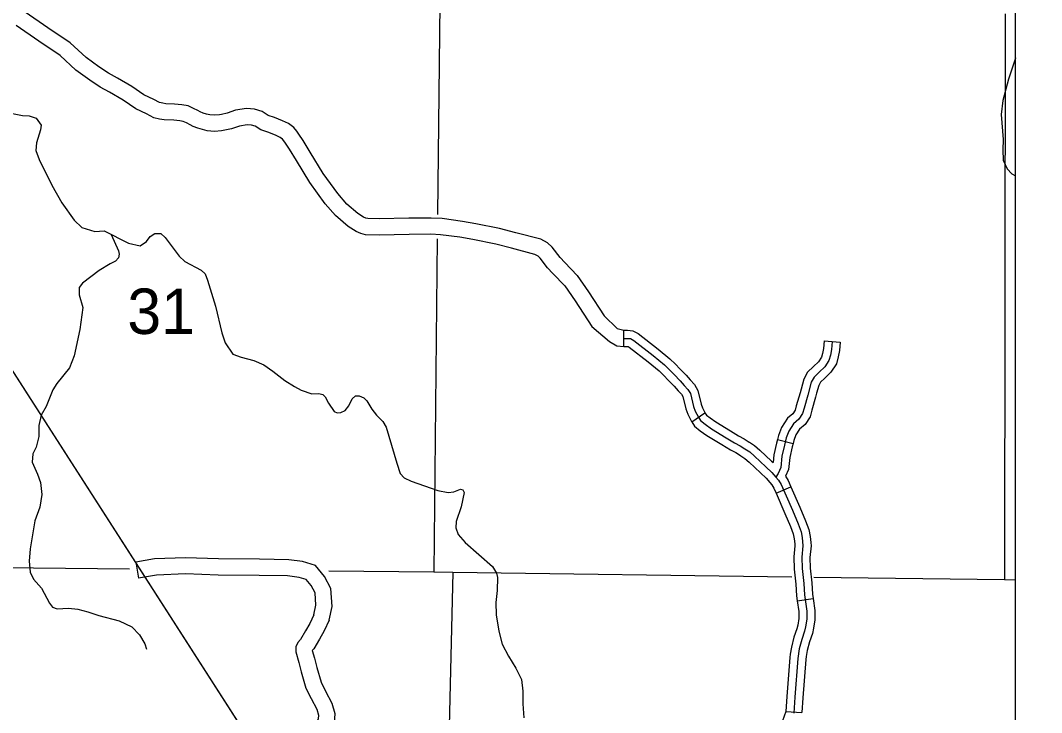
# Model space of a CAD drawing. Extents: x 0 to 3171, y 0 to 2059.
# Drawn here: x 1965.7 to 2123.9, y 1087.6 to 1194.8 of the extents above; entities that cross this region are included whole.
import ezdxf

# ---------------------------------------------------------------- set-up
doc = ezdxf.new("R2010")
doc.units = 0
for name, color, linetype in [('Default', 7, 'Continuous'), ('Level 35', 7, 'Continuous'), ('Level 4', 7, 'Continuous'), ('Level 45', 7, 'Continuous'), ('Level 46', 7, 'Continuous'), ('Level 5', 7, 'Continuous')]:
    doc.layers.add(name, color=color, linetype=linetype)

msp = doc.modelspace()

# ---------------------------------------------------------------- linework, layer by layer
at = {"layer": 'Default'}
msp.add_line((2119.81, 254.41), (2119.81, 1254.61), dxfattribs=at)
msp.add_lwpolyline([(2119.81, 1254.61), (1029.42, 1254.61), (1029.42, 254.41), (2119.81, 254.41)], close=True, dxfattribs=at)
msp.add_lwpolyline([(2119.81, 1254.61), (1029.42, 1254.61), (1029.42, 254.41), (2119.81, 254.41)], close=True, dxfattribs=at)
msp.add_lwpolyline([(2119.81, 1254.61), (1029.42, 1254.61), (1029.42, 254.41), (2119.81, 254.41)], close=True, dxfattribs=at)
for points in [[(1931.87, 1191.31), (2273.76, 658.86), (2637.04, 658.32)], [(1931.87, 1191.31), (2119.81, 898.62)]]:
    msp.add_lwpolyline(points, dxfattribs=at)
at = {"layer": 'Level 35'}
for points in [[(2119.81, 1189), (2119.8, 1188.95), (2118.71, 1185.67), (2117.83, 1182.41), (2117.59, 1180.23), (2117.92, 1176.37), (2117.86, 1174.76), (2117.91, 1173.16), (2118.5, 1171.83), (2119.26, 1171.04), (2119.81, 1170.7)], [(1964.24, 1180.44), (1966.09, 1180.09), (1967.12, 1179.99), (1968.18, 1179.67), (1968.94, 1178.59), (1968.83, 1177.84), (1968.26, 1175.81), (1968.14, 1174.63), (1968.63, 1173.23), (1970.63, 1169.27), (1972.16, 1166.53), (1974.08, 1163.85), (1975.24, 1162.73), (1977.26, 1162.1), (1978.71, 1162.19), (1982.5, 1160.31), (1984.27, 1159.87), (1985.28, 1160.53), (1985.84, 1161.32), (1986.56, 1161.8), (1987.48, 1161.79), (1988.15, 1161.17), (1990.32, 1158.29), (1991.2, 1157.48), (1993.73, 1156.09), (1994.34, 1155.55), (1994.72, 1154.59), (1995.97, 1150.53), (1996.94, 1146.4), (1997.44, 1144.84), (1998.66, 1143.1), (1999.9, 1142.65), (2001.87, 1142.12), (2003.41, 1141.46), (2004.84, 1140.48), (2006.69, 1139.05), (2008.17, 1138.1), (2009.21, 1137.54), (2010.89, 1136.96), (2011.95, 1137.04), (2012.55, 1136.86), (2012.92, 1136.52), (2013.47, 1135.51), (2014.32, 1134.25), (2014.8, 1134.04), (2015.37, 1134.06), (2016.02, 1134.37), (2016.59, 1135.13), (2017.13, 1136.17), (2017.62, 1136.64), (2018.2, 1136.66), (2018.94, 1136.37), (2019.36, 1135.89), (2020.15, 1134.59), (2020.87, 1133.66), (2021.87, 1132.69), (2022.4, 1131.78), (2024.02, 1126.22), (2024.55, 1124.64), (2025.15, 1123.95), (2026.23, 1123.46), (2030.35, 1121.99), (2031.97, 1121.68), (2032.84, 1121.81), (2033.91, 1122.2), (2034.27, 1122.09), (2034.47, 1121.71), (2033.97, 1119.48), (2033.21, 1117.17), (2033.14, 1116.19)], [(1979.82, 1161.63), (1980.92, 1159.11), (1981.02, 1158.59), (1980.93, 1158.01), (1980.49, 1157.52), (1979.63, 1157.11), (1977.94, 1156.05), (1976.65, 1155.09), (1975.35, 1154.09), (1974.86, 1153.43), (1974.84, 1152.28), (1975.39, 1150.35), (1974.97, 1146.94), (1974.07, 1142.87), (1973.33, 1140.98), (1971.38, 1138.59), (1970.76, 1137.56), (1969.71, 1134.98), (1968.96, 1133.67), (1968.61, 1132.06), (1968.62, 1130.36), (1968.19, 1128.72), (1967.65, 1127.69), (1967.57, 1126.39), (1968.37, 1124.55), (1968.84, 1123.24), (1969.06, 1121.4), (1968.74, 1119.41), (1967.96, 1117.32), (1967.27, 1112.97), (1967.11, 1111.03), (1967.25, 1109.37), (1967.79, 1108.26), (1969.01, 1106.89), (1970.24, 1104.55), (1970.73, 1103.94), (1971.45, 1103.69), (1973.2, 1103.75), (1974.65, 1103.62), (1976.17, 1103.22), (1977.89, 1102.62), (1981.04, 1101.82), (1982.98, 1100.9), (1984.16, 1099.64), (1985.03, 1098.23), (1985.29, 1097.42)], [(2033.14, 1116.19), (2033.5, 1115.17), (2034.6, 1113.93), (2038.85, 1110.21), (2039.48, 1109.2), (2039.6, 1108.55), (2039.54, 1106.5), (2039.37, 1104.63), (2039.39, 1102.73), (2039.81, 1100.2), (2040.36, 1098.18), (2041.3, 1096.34), (2042.46, 1094.5), (2043.33, 1092.71), (2043.51, 1090.91), (2043.53, 1088.98), (2043.67, 1086.79)]]:
    msp.add_lwpolyline(points, dxfattribs=at)
at = {"layer": 'Level 4'}
for points in [[(1982.64, 1109.82), (1952.86, 1110.13)], [(2085.16, 1108.59), (2032.69, 1109.29), (2029.77, 1109.33), (2013.52, 1109.5)], [(2119.81, 1108.12), (2118.11, 1108.14), (2088.58, 1108.54)]]:
    msp.add_lwpolyline(points, dxfattribs=at)
at = {"layer": 'Level 45'}
for p, q in [((2059.17, 1144.3), (2059.17, 1146.8)), ((2090.17, 1145.16), (2092.66, 1144.99)), ((2069.69, 1132.61), (2071.74, 1134.03)), ((2082.95, 1129.88), (2085.38, 1129.29)), ((2082.76, 1121.58), (2085.05, 1122.58)), ((2086.02, 1104.91), (2088.5, 1105.25)), ((2084.24, 1087.78), (2086.73, 1087.61))]:
    msp.add_line(p, q, dxfattribs=at)
for points in [[(2059.17, 1146.8), (2059.73, 1146.8), (2060.58, 1146.73), (2061.39, 1146.29), (2064.48, 1143.86), (2066.31, 1142.4), (2067.15, 1141.54)], [(2059.17, 1145.55), (2059.68, 1145.55), (2060.21, 1145.51), (2060.7, 1145.24), (2063.7, 1142.89), (2065.47, 1141.47), (2066.95, 1139.96), (2067.88, 1139), (2068.52, 1138.27), (2069.1, 1137.66), (2069.47, 1137.01), (2069.96, 1135.02), (2070.22, 1134.29), (2070.71, 1133.33), (2071.06, 1132.82), (2071.77, 1132.25), (2072.74, 1131.56), (2075.02, 1130.17), (2076.3, 1129.4), (2077.16, 1128.93), (2077.91, 1128.45), (2078.66, 1127.96), (2079.42, 1127.31), (2081.18, 1125.65), (2082.11, 1124.77), (2082.73, 1124.08), (2083.11, 1123.62), (2083.53, 1122.95), (2085.27, 1118.95), (2086.15, 1116.86), (2086.62, 1115.61), (2086.8, 1114.71), (2086.91, 1113.42), (2086.73, 1111.68), (2086.8, 1109.91), (2087.02, 1107.58), (2087.16, 1105.83), (2087.5, 1103.32), (2087.5, 1102.06), (2087.32, 1100.91), (2087.16, 1100.22), (2086.71, 1098.94), (2086.33, 1097.47), (2086.11, 1095.99), (2085.65, 1089.99), (2085.47, 1087.52)], [(2091.41, 1145.07), (2091.33, 1143.84), (2091.15, 1142.95), (2090.93, 1142.11), (2090.27, 1141.14), (2089.43, 1140.3), (2088.63, 1139.55), (2088.19, 1138.75), (2087.66, 1136.76), (2087.08, 1134.77), (2086.86, 1133.93), (2086.29, 1133.05), (2085.45, 1132.34), (2084.7, 1131.19), (2084.3, 1130.13), (2084.03, 1129.02), (2083.64, 1127.3), (2083.46, 1125.57), (2083.06, 1124.65), (2082.73, 1124.08)], [(2090.17, 1145.16), (2090.09, 1144), (2089.93, 1143.23), (2089.77, 1142.64), (2089.3, 1141.94), (2088.55, 1141.19), (2087.63, 1140.32), (2087.02, 1139.22), (2086.62, 1137.7)], [(2092.66, 1144.99), (2092.57, 1143.67), (2092.37, 1142.67), (2092.08, 1141.59), (2091.23, 1140.34), (2090.3, 1139.4), (2089.63, 1138.77), (2089.36, 1138.28), (2089.03, 1137.06)], [(2059.17, 1144.3), (2059.63, 1144.3), (2059.85, 1144.28), (2060.01, 1144.19), (2062.93, 1141.91), (2064.63, 1140.54), (2065.37, 1139.79)], [(2067.15, 1141.54), (2067.85, 1140.83), (2068.8, 1139.85), (2069.45, 1139.11), (2070.1, 1138.41), (2070.64, 1137.49), (2071.16, 1135.39), (2071.37, 1134.79), (2071.78, 1133.98), (2071.74, 1134.03)], [(2065.37, 1139.79), (2066.06, 1139.09), (2066.96, 1138.15), (2067.59, 1137.44), (2068.09, 1136.91), (2068.3, 1136.54), (2068.76, 1134.66), (2069.07, 1133.8), (2069.63, 1132.69), (2069.69, 1132.61)], [(2086.62, 1137.7), (2086.45, 1137.1), (2085.88, 1135.1), (2085.7, 1134.44), (2085.34, 1133.88), (2084.5, 1133.18), (2083.58, 1131.76), (2083.1, 1130.49), (2082.95, 1129.88)], [(2089.03, 1137.06), (2088.86, 1136.43), (2088.29, 1134.44), (2088.02, 1133.42), (2087.24, 1132.21), (2086.39, 1131.5), (2085.82, 1130.62), (2085.5, 1129.76), (2085.38, 1129.29)], [(2071.74, 1134.03), (2071.99, 1133.68), (2072.52, 1133.25), (2073.43, 1132.61), (2075.67, 1131.24), (2076.92, 1130.48), (2077.8, 1130.01), (2078.59, 1129.5), (2078.64, 1129.47)], [(2069.69, 1132.61), (2070.14, 1131.97), (2071.01, 1131.25), (2072.05, 1130.52), (2074.37, 1129.1), (2075.68, 1128.31), (2076.52, 1127.86), (2077.23, 1127.4), (2077.28, 1127.37)], [(2078.64, 1129.47), (2079.42, 1128.96), (2080.25, 1128.24), (2082.04, 1126.56), (2082.28, 1126.33)], [(2082.95, 1129.88), (2082.82, 1129.31), (2082.4, 1127.5), (2082.28, 1126.33)], [(2085.38, 1129.29), (2085.25, 1128.74), (2084.87, 1127.09), (2084.68, 1125.25), (2084.22, 1124.19)], [(2077.28, 1127.37), (2077.91, 1126.96), (2078.58, 1126.38), (2080.32, 1124.74), (2081.21, 1123.89), (2081.78, 1123.26), (2082.09, 1122.88), (2082.42, 1122.36), (2082.76, 1121.58)], [(2084.22, 1124.19), (2084.63, 1123.54), (2085.05, 1122.58)], [(2085.05, 1122.58), (2086.42, 1119.44), (2087.32, 1117.32), (2087.83, 1115.95), (2088.04, 1114.88), (2088.12, 1113.95)], [(2082.76, 1121.58), (2084.12, 1118.46), (2084.99, 1116.4), (2085.41, 1115.27), (2085.56, 1114.53), (2085.63, 1113.74)], [(2085.63, 1113.74), (2085.65, 1113.43), (2085.48, 1111.72), (2085.55, 1109.83), (2085.78, 1107.47), (2085.92, 1105.69), (2086.02, 1104.91)], [(2088.12, 1113.95), (2088.16, 1113.41), (2087.98, 1111.64), (2088.04, 1109.99), (2088.27, 1107.69), (2088.4, 1105.96), (2088.5, 1105.25)], [(2088.5, 1105.25), (2088.75, 1103.41), (2088.75, 1101.96), (2088.55, 1100.66), (2088.36, 1099.87), (2087.91, 1098.58), (2087.56, 1097.22), (2087.41, 1096.28)], [(2086.02, 1104.91), (2086.25, 1103.24), (2086.25, 1102.16), (2086.09, 1101.15), (2085.96, 1100.57), (2085.52, 1099.3), (2085.11, 1097.72), (2084.94, 1096.66)], [(2084.94, 1096.66), (2084.86, 1096.13), (2084.4, 1090.09), (2084.24, 1087.78)], [(2087.41, 1096.28), (2087.35, 1095.85), (2086.89, 1089.9), (2086.73, 1087.61)], [(2084.24, 1087.78), (2084.24, 1087.78), (2083.21, 1084.88), (2081.87, 1081.57), (2081.32, 1080.42), (2081.15, 1080.08)]]:
    msp.add_lwpolyline(points, dxfattribs=at)
at = {"layer": 'Level 46'}
for points in [[(2051.96, 1155.27), (2050.02, 1157.29), (2049.3, 1158.09), (2048.08, 1159.7), (2047.34, 1160.35), (2046.31, 1160.89), (2042.43, 1161.91), (2039.91, 1162.58), (2036.27, 1163.31), (2034.17, 1163.67), (2031.02, 1164.1), (2029.35, 1164.19), (2025.88, 1164.15), (2021.28, 1164.06), (2019.55, 1164.09), (2019.24, 1164.18), (2018.87, 1164.33), (2017.97, 1164.89), (2016.31, 1166.35), (2014.89, 1167.98), (2012.63, 1171.06), (2010.62, 1174.39), (2009.53, 1176.21), (2008.87, 1177.19), (2008.54, 1177.66), (2008.09, 1178.2), (2007.24, 1178.85), (2006.31, 1179.26), (2005.06, 1179.75), (2004.1, 1180.09), (2003.18, 1180.68), (2002, 1181.05), (2000.75, 1181.14), (1999.07, 1180.87), (1997.75, 1180.43), (1996.9, 1180.23), (1996.57, 1180.18), (1995.79, 1180.11), (1995.06, 1180.17), (1994.57, 1180.29), (1994.06, 1180.44), (1993.56, 1180.65), (1993.2, 1180.84), (1992.55, 1181.17), (1991.71, 1181.54), (1990.74, 1181.74), (1989.62, 1181.81), (1988.25, 1181.87), (1987.79, 1181.95), (1987.28, 1182.07), (1986.38, 1182.54), (1984.86, 1183.28), (1983, 1184.53), (1980.77, 1185.85), (1979.39, 1186.6), (1977.91, 1187.58), (1975.94, 1189.02), (1973.44, 1191.31), (1969.99, 1193.63), (1966.47, 1196.07)], [(2050.02, 1153.67), (2048.19, 1155.59), (2047.37, 1156.5), (2046.24, 1157.99), (2045.91, 1158.28), (2045.4, 1158.55), (2041.79, 1159.5), (2039.35, 1160.14), (2035.81, 1160.86), (2033.79, 1161.2), (2030.79, 1161.61), (2029.3, 1161.69), (2025.92, 1161.65), (2021.28, 1161.56), (2019.19, 1161.6), (2018.43, 1161.81), (2017.73, 1162.09), (2016.47, 1162.88), (2014.53, 1164.58), (2012.93, 1166.41), (2010.54, 1169.67), (2008.48, 1173.1), (2007.42, 1174.87), (2006.81, 1175.77), (2006.55, 1176.15), (2006.35, 1176.38), (2005.96, 1176.68), (2005.34, 1176.96), (2004.19, 1177.41), (2002.99, 1177.83), (2002.11, 1178.4), (2001.54, 1178.58), (2000.86, 1178.62), (1999.67, 1178.43), (1998.42, 1178.02), (1997.39, 1177.78), (1996.89, 1177.7), (1995.79, 1177.6), (1994.64, 1177.7), (1993.92, 1177.88), (1993.24, 1178.08), (1992.5, 1178.38), (1992.04, 1178.62), (1991.47, 1178.92), (1990.95, 1179.15), (1990.41, 1179.26), (1989.48, 1179.32), (1987.98, 1179.38), (1987.29, 1179.5), (1986.39, 1179.72), (1985.25, 1180.31), (1983.61, 1181.11), (1981.67, 1182.42), (1979.53, 1183.67), (1978.09, 1184.46), (1976.48, 1185.53), (1974.35, 1187.08), (1971.89, 1189.34), (1968.58, 1191.56), (1965.08, 1194)], [(2051.96, 1155.27), (2053.72, 1152.78), (2056.14, 1149.05), (2058.13, 1147.07), (2059.17, 1146.8)], [(2050.02, 1153.67), (2051.65, 1151.38), (2054.24, 1147.38), (2056.97, 1145.07), (2058.09, 1144.42), (2059.17, 1144.3)], [(2013.57, 1101.91), (2014.03, 1104.05), (2013.81, 1106.84), (2012.84, 1108.7), (2011.41, 1110.38), (2009.44, 1111.01), (2007.28, 1111.28), (2002.74, 1111.34), (1996.43, 1111.4), (1991.31, 1111.59), (1986.53, 1111.4), (1983.6, 1110.89), (1984.02, 1108.42)], [(2011.19, 1102.74), (2011.51, 1104.22), (2011.36, 1106.14), (2010.75, 1107.3), (2009.97, 1108.21), (2008.91, 1108.55), (2007.1, 1108.78), (2002.71, 1108.84), (1996.37, 1108.9), (1991.32, 1109.09), (1986.8, 1108.91), (1984.02, 1108.42)], [(2011.19, 1102.74), (2010.54, 1101.41), (2009.88, 1100.26), (2009.1, 1098.94), (2008.71, 1098.47), (2008.37, 1097.79), (2008.37, 1097.03), (2008.84, 1095.37), (2009.21, 1093.91), (2009.96, 1091.41), (2010.74, 1089.78), (2011.62, 1088.15), (2011.89, 1087.19), (2011.85, 1086.62), (2011.62, 1086.13), (2010, 1084.7), (2007.24, 1082.09), (2004.73, 1079.72)], [(2013.57, 1101.91), (2012.75, 1100.24), (2012.04, 1099), (2011.15, 1097.49), (2010.92, 1097.21), (2011.26, 1096.01), (2011.62, 1094.58), (2012.3, 1092.32), (2012.97, 1090.92), (2013.96, 1089.09), (2014.41, 1087.44), (2014.31, 1085.99), (2013.67, 1084.61), (2011.69, 1082.86), (2008.96, 1080.27), (2006.57, 1078.03)]]:
    msp.add_lwpolyline(points, dxfattribs=at)
at = {"layer": 'Level 5'}
for points in [[(2030.66, 1197.39), (2030.33, 1164.73)], [(2118.21, 1195.83), (2118.11, 1108.14)], [(2030.29, 1160.96), (2029.77, 1109.33)], [(2032.69, 1109.29), (2030.71, 1024.79)]]:
    msp.add_lwpolyline(points, dxfattribs=at)

# ---------------------------------------------------------------- texts
msp.add_text('31', height=7.04, dxfattribs=at).set_placement((1982.3, 1146.23))

doc.saveas('drawing.dxf')
